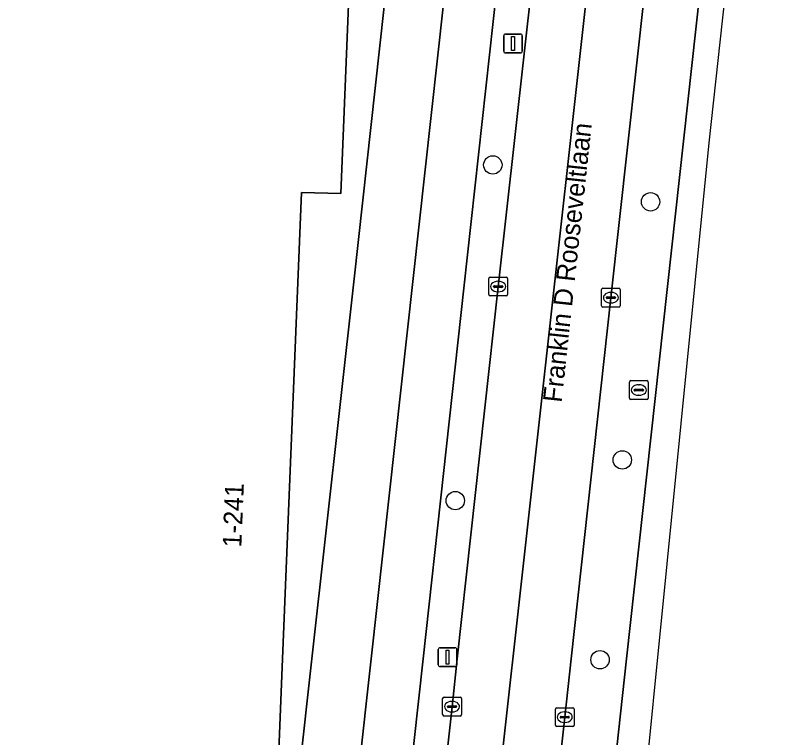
# Model space of a CAD drawing. Extents: x 160888 to 161385, y 386490 to 386908.
# Drawn here: x 161343.3 to 161384.03, y 386745.8 to 386784.23 of the extents above; entities that cross this region are included whole.
import ezdxf

# ---------------------------------------------------------------- set-up
doc = ezdxf.new("R2010")
doc.units = 0
for name, color, linetype in [('IMGEO_Berm_groen', 7, 'Continuous'), ('IMGEO_Boom', 7, 'Continuous'), ('IMGEO_Erf', 7, 'Continuous'), ('IMGEO_Fietspad_gesloten', 7, 'Continuous'), ('IMGEO_Kolk', 7, 'Continuous'), ('IMGEO_Lichtmast', 7, 'Continuous'), ('IMGEO_Openbare_ruimte_label', 7, 'Continuous'), ('IMGEO_Pand', 7, 'Continuous'), ('IMGEO_Pand_nummerreeks', 7, 'Continuous'), ('IMGEO_Rijbaan_lokaal_gesloten', 7, 'Continuous'), ('IMGEO_Rioolput', 7, 'Continuous'), ('IMGEO_Voetpad_open', 7, 'Continuous')]:
    doc.layers.add(name, color=color, linetype=linetype)

msp = doc.modelspace()

# ---------------------------------------------------------------- linework, layer by layer
at = {"layer": 'IMGEO_Berm_groen'}
for points in [[(161373.644, 386813.676), (161372.043, 386813.873), (161371.658, 386810.524), (161367.179, 386769.719), (161365.004, 386750), (161363.779, 386738.891), (161362.922, 386732.791), (161361.755, 386725.593)], [(161368.999, 386769.786), (161371.264, 386790.142), (161373.505, 386810.507), (161373.654, 386811.717), (161373.847, 386812.791), (161373.931, 386813.306)], [(161379.812, 386812.698), (161379.518, 386809.955), (161377.255, 386789.585), (161374.998, 386769.209), (161372.886, 386750), (161372.544, 386746.889), (161370.136, 386725.225)], [(161373.249, 386724.98), (161374.104, 386730.63), (161374.587, 386736.651), (161374.749, 386740.065), (161375.512, 386747.068), (161375.835, 386750), (161380.179, 386789.468)], [(161364.089, 386725.334), (161364.11, 386725.435), (161364.289, 386727.081), (161366.545, 386747.443), (161366.826, 386750), (161368.999, 386769.786)]]:
    msp.add_lwpolyline(points, dxfattribs=at)
at = {"layer": 'IMGEO_Boom'}
for centre in [(161368.715, 386776.272), (161377.108, 386774.309), (161375.606, 386760.578), (161366.718, 386758.41), (161374.42, 386749.942)]:
    msp.add_circle(centre, 0.489, dxfattribs=at)
at = {"layer": 'IMGEO_Erf'}
msp.add_lwpolyline([(161362.7, 386825.861), (161360.635, 386774.751), (161358.531, 386774.8), (161357.522, 386750), (161357.179, 386741.563), (161353.533, 386741.712), (161353.387, 386738.115), (161355.121, 386738.044), (161354.593, 386725.304), (161356.352, 386725.232), (161358.409, 386743.907), (161359.085, 386750), (161361.328, 386770.209), (161365.845, 386811.132), (161367.463, 386825.61)], close=True, dxfattribs=at)
at = {"layer": 'IMGEO_Fietspad_gesloten'}
for points in [[(161367.179, 386769.719), (161371.658, 386810.524), (161372.043, 386813.873), (161372.393, 386816.844), (161372.67, 386819.166), (161373.331, 386824.71), (161370.327, 386824.774)], [(161370.409, 386823.612), (161369.942, 386819.493), (161368.96, 386810.871), (161362.241, 386750), (161360.898, 386737.834), (161359.269, 386727.112)], [(161361.755, 386725.593), (161362.922, 386732.791), (161363.779, 386738.891), (161365.004, 386750), (161367.179, 386769.719)]]:
    msp.add_lwpolyline(points, dxfattribs=at)
at = {"layer": 'IMGEO_Kolk'}
for p, q in [((161368.574, 386770.299), (161369.426, 386770.299)), ((161368.499, 386769.373), (161368.499, 386770.225)), ((161368.987, 386770.079), (161369.012, 386770.079)), ((161369.5, 386770.225), (161369.5, 386769.373)), ((161368.758, 386769.793), (161368.758, 386769.805)), ((161369.196, 386769.756), (161368.798, 386769.756)), ((161368.801, 386769.842), (161369.199, 386769.842)), ((161369.01, 386769.519), (161368.985, 386769.519)), ((161369.242, 386769.805), (161369.242, 386769.793)), ((161374.497, 386768.783), (161374.497, 386769.635)), ((161374.572, 386769.709), (161375.424, 386769.709)), ((161374.985, 386769.489), (161375.01, 386769.489)), ((161375.498, 386769.635), (161375.498, 386768.783)), ((161369.426, 386769.299), (161368.574, 386769.299)), ((161374.756, 386769.203), (161374.756, 386769.215)), ((161375.194, 386769.166), (161374.796, 386769.166)), ((161374.799, 386769.252), (161375.197, 386769.252)), ((161375.24, 386769.215), (161375.24, 386769.203)), ((161375.424, 386768.709), (161374.572, 386768.709)), ((161375.008, 386768.929), (161374.983, 386768.929)), ((161366.044, 386747.022), (161366.044, 386747.874)), ((161366.119, 386747.948), (161366.971, 386747.948)), ((161367.045, 386747.874), (161367.045, 386747.022)), ((161366.303, 386747.442), (161366.303, 386747.454)), ((161366.346, 386747.491), (161366.744, 386747.491)), ((161366.532, 386747.728), (161366.557, 386747.728)), ((161366.787, 386747.454), (161366.787, 386747.442)), ((161366.741, 386747.405), (161366.343, 386747.405)), ((161366.555, 386747.168), (161366.53, 386747.168)), ((161372.043, 386746.463), (161372.043, 386747.315)), ((161372.118, 386747.389), (161372.97, 386747.389)), ((161372.531, 386747.169), (161372.556, 386747.169)), ((161373.044, 386747.315), (161373.044, 386746.463)), ((161366.971, 386746.948), (161366.119, 386746.948)), ((161372.302, 386746.883), (161372.302, 386746.895)), ((161372.74, 386746.846), (161372.342, 386746.846)), ((161372.345, 386746.932), (161372.743, 386746.932)), ((161372.786, 386746.895), (161372.786, 386746.883)), ((161372.97, 386746.389), (161372.118, 386746.389)), ((161372.554, 386746.609), (161372.529, 386746.609))]:
    msp.add_line(p, q, dxfattribs=at)
for points in [[(161368.574, 386770.299), (161369.426, 386770.299)], [(161368.499, 386769.373), (161368.499, 386770.225)], [(161369.5, 386770.225), (161369.5, 386769.373)], [(161374.497, 386768.783), (161374.497, 386769.635)], [(161374.572, 386769.709), (161375.424, 386769.709)], [(161375.498, 386769.635), (161375.498, 386768.783)], [(161369.426, 386769.299), (161368.574, 386769.299)], [(161375.424, 386768.709), (161374.572, 386768.709)], [(161366.044, 386747.022), (161366.044, 386747.874)], [(161366.119, 386747.948), (161366.971, 386747.948)], [(161367.045, 386747.874), (161367.045, 386747.022)], [(161372.043, 386746.463), (161372.043, 386747.315)], [(161372.118, 386747.389), (161372.97, 386747.389)], [(161373.044, 386747.315), (161373.044, 386746.463)], [(161366.971, 386746.948), (161366.119, 386746.948)], [(161372.97, 386746.389), (161372.118, 386746.389)]]:
    msp.add_lwpolyline(points, dxfattribs=at)
for centre, radius, start, end in [((161368.576, 386770.223), 0.0765, 91.552, 178.448), ((161368.576, 386770.223), 0.0765, 91.552, 178.448), ((161369.424, 386770.223), 0.0765, 1.552, 88.448), ((161369.424, 386770.223), 0.0765, 1.552, 88.448), ((161368.798, 386769.802), 0.0403, 85.8775, 175.7526), ((161368.795, 386769.792), 0.0366, 178.938, 274.7102), ((161369.199, 386769.799), 0.043, 264.8664, 352.4533), ((161369.203, 386769.804), 0.0386, 1.7309, 96.639), ((161374.574, 386769.633), 0.0765, 91.552, 178.448), ((161374.574, 386769.633), 0.0765, 91.552, 178.448), ((161375.422, 386769.633), 0.0765, 1.552, 88.448), ((161375.422, 386769.633), 0.0765, 1.552, 88.448), ((161368.576, 386769.375), 0.0765, 181.552, 268.448), ((161368.576, 386769.375), 0.0765, 181.552, 268.448), ((161369.424, 386769.375), 0.0765, 271.552, 358.448), ((161369.424, 386769.375), 0.0765, 271.552, 358.448), ((161374.796, 386769.212), 0.0403, 85.8775, 175.7526), ((161374.793, 386769.202), 0.0366, 178.938, 274.7102), ((161375.197, 386769.209), 0.043, 264.8664, 352.4533), ((161375.201, 386769.214), 0.0386, 1.7309, 96.639), ((161374.574, 386768.785), 0.0765, 181.552, 268.448), ((161374.574, 386768.785), 0.0765, 181.552, 268.448), ((161375.422, 386768.785), 0.0765, 271.552, 358.448), ((161375.422, 386768.785), 0.0765, 271.552, 358.448), ((161366.121, 386747.872), 0.0765, 91.552, 178.448), ((161366.121, 386747.872), 0.0765, 91.552, 178.448), ((161366.969, 386747.872), 0.0765, 1.552, 88.448), ((161366.969, 386747.872), 0.0765, 1.552, 88.448), ((161366.343, 386747.451), 0.0403, 85.8775, 175.7526), ((161366.748, 386747.453), 0.0386, 1.7309, 96.639), ((161366.34, 386747.441), 0.0366, 178.938, 274.7102), ((161366.744, 386747.448), 0.043, 264.8664, 352.4533), ((161372.12, 386747.313), 0.0765, 91.552, 178.448), ((161372.12, 386747.313), 0.0765, 91.552, 178.448), ((161372.968, 386747.313), 0.0765, 1.552, 88.448), ((161372.968, 386747.313), 0.0765, 1.552, 88.448), ((161366.121, 386747.024), 0.0765, 181.552, 268.448), ((161366.121, 386747.024), 0.0765, 181.552, 268.448), ((161366.969, 386747.024), 0.0765, 271.552, 358.448), ((161366.969, 386747.024), 0.0765, 271.552, 358.448), ((161372.342, 386746.892), 0.0403, 85.8775, 175.7526), ((161372.339, 386746.882), 0.0366, 178.938, 274.7102), ((161372.743, 386746.889), 0.043, 264.8664, 352.4533), ((161372.747, 386746.894), 0.0386, 1.7309, 96.639), ((161372.12, 386746.465), 0.0765, 181.552, 268.448), ((161372.12, 386746.465), 0.0765, 181.552, 268.448), ((161372.968, 386746.465), 0.0765, 271.552, 358.448), ((161372.968, 386746.465), 0.0765, 271.552, 358.448)]:
    msp.add_arc(centre, radius, start, end, dxfattribs=at)
for centre, major_axis, ratio, start_param, end_param in [((161368.986, 386769.799), (-0.387, 0.002), 0.722429, 4.712389, 7.853982), ((161369.011, 386769.799), (-0.39, 0.002), 0.717154, 1.570796, 4.712389), ((161374.984, 386769.209), (-0.387, 0.002), 0.722429, 4.712389, 7.853982), ((161375.009, 386769.209), (-0.39, 0.002), 0.717154, 1.570796, 4.712389), ((161366.531, 386747.448), (-0.387, 0.002), 0.722429, 4.712389, 7.853982), ((161366.556, 386747.448), (-0.39, 0.002), 0.717154, 1.570796, 4.712389), ((161372.53, 386746.889), (-0.387, 0.002), 0.722429, 4.712389, 7.853982), ((161372.555, 386746.889), (-0.39, 0.002), 0.717154, 1.570796, 4.712389)]:
    msp.add_ellipse(centre, major_axis=major_axis, ratio=ratio, start_param=start_param, end_param=end_param, dxfattribs=at)
at = {"layer": 'IMGEO_Lichtmast'}
for p, q in [((161369.295, 386782.332), (161369.295, 386783.132)), ((161369.295, 386783.132), (161369.295, 386782.332)), ((161369.395, 386783.232), (161370.185, 386783.232)), ((161370.185, 386783.232), (161369.395, 386783.232)), ((161370.285, 386783.132), (161370.285, 386782.332)), ((161370.285, 386782.332), (161370.285, 386783.132)), ((161370.185, 386782.232), (161369.395, 386782.232)), ((161369.395, 386782.232), (161370.185, 386782.232)), ((161365.81, 386749.681), (161365.81, 386750.481)), ((161365.81, 386750.481), (161365.81, 386749.681)), ((161365.91, 386750.581), (161366.7, 386750.581)), ((161366.7, 386750.581), (161365.91, 386750.581)), ((161366.8, 386750.481), (161366.8, 386749.681)), ((161366.8, 386749.681), (161366.8, 386750.481)), ((161366.7, 386749.581), (161365.91, 386749.581)), ((161365.91, 386749.581), (161366.7, 386749.581))]:
    msp.add_line(p, q, dxfattribs=at)
for points in [[(161369.715, 386783.107), (161369.865, 386783.107), (161369.865, 386782.357), (161369.715, 386782.357), (161369.715, 386783.107)], [(161366.23, 386750.456), (161366.38, 386750.456), (161366.38, 386749.706), (161366.23, 386749.706), (161366.23, 386750.456)]]:
    msp.add_lwpolyline(points, dxfattribs=at)
for centre, start, end in [((161369.395, 386783.132), 90, 180), ((161369.395, 386783.132), 90, 180), ((161370.185, 386783.132), 0, 90), ((161370.185, 386783.132), 360, 90), ((161369.395, 386782.332), 180, 270), ((161369.395, 386782.332), 180, 270), ((161370.185, 386782.332), 270, 0), ((161370.185, 386782.332), 270, 0), ((161365.91, 386750.481), 90, 180), ((161365.91, 386750.481), 90, 180), ((161366.7, 386750.481), 0, 90), ((161366.7, 386750.481), 360, 90), ((161365.91, 386749.681), 180, 270), ((161365.91, 386749.681), 180, 270), ((161366.7, 386749.681), 270, 0), ((161366.7, 386749.681), 270, 0)]:
    msp.add_arc(centre, 0.1, start, end, dxfattribs=at)
at = {"layer": 'IMGEO_Pand'}
msp.add_lwpolyline([(161348.445, 386826.44), (161348.244, 386822.153), (161340.54, 386822.467), (161340.189, 386813.832), (161342.162, 386813.752), (161340.481, 386772.426), (161338.482, 386772.507), (161337.567, 386750), (161337.283, 386743.017), (161335.309, 386743.098), (161334.593, 386726.104), (161334.801, 386726.096), (161354.391, 386725.312), (161354.593, 386725.304), (161355.121, 386738.044), (161353.387, 386738.115), (161353.533, 386741.712), (161357.179, 386741.563), (161357.522, 386750), (161358.531, 386774.8), (161360.635, 386774.751), (161362.7, 386825.861)], close=True, dxfattribs=at)
at = {"layer": 'IMGEO_Rijbaan_lokaal_gesloten'}
msp.add_lwpolyline([(161368.323, 386736.898), (161376.784, 386813.011), (161373.931, 386813.306), (161373.847, 386812.791), (161373.654, 386811.717), (161373.505, 386810.507), (161371.264, 386790.142), (161368.999, 386769.786), (161366.826, 386750), (161366.545, 386747.443), (161364.289, 386727.081), (161364.11, 386725.435), (161364.089, 386725.334), (161363.501, 386722.441), (161363.674, 386722.44)], dxfattribs=at)
for points in [[(161372.544, 386746.889), (161372.886, 386750), (161374.998, 386769.209), (161377.255, 386789.585), (161379.518, 386809.955), (161379.812, 386812.698), (161376.784, 386813.011), (161368.323, 386736.898), (161366.259, 386718.291), (161369.328, 386718.155), (161369.778, 386722.177), (161370.136, 386725.225)], [(161374.289, 386717.883), (161380.225, 386777.448), (161384.035, 386812.351), (161382.706, 386812.365), (161380.179, 386789.468), (161375.835, 386750), (161375.512, 386747.068), (161374.749, 386740.065), (161374.587, 386736.651), (161374.104, 386730.63), (161373.249, 386724.98), (161372.62, 386721.998), (161371.548, 386717.899)]]:
    msp.add_lwpolyline(points, close=True, dxfattribs=at)
at = {"layer": 'IMGEO_Rioolput'}
for p, q in [((161375.983, 386763.867), (161375.983, 386764.719)), ((161376.058, 386764.793), (161376.91, 386764.793)), ((161376.471, 386764.573), (161376.496, 386764.573)), ((161376.984, 386764.719), (161376.984, 386763.867)), ((161376.242, 386764.287), (161376.242, 386764.299)), ((161376.68, 386764.25), (161376.282, 386764.25)), ((161376.285, 386764.336), (161376.683, 386764.336)), ((161376.726, 386764.299), (161376.726, 386764.287)), ((161376.91, 386763.793), (161376.058, 386763.793)), ((161376.494, 386764.013), (161376.469, 386764.013))]:
    msp.add_line(p, q, dxfattribs=at)
for points in [[(161375.983, 386763.867), (161375.983, 386764.719)], [(161376.058, 386764.793), (161376.91, 386764.793)], [(161376.984, 386764.719), (161376.984, 386763.867)], [(161376.91, 386763.793), (161376.058, 386763.793)]]:
    msp.add_lwpolyline(points, dxfattribs=at)
for centre, radius, start, end in [((161376.06, 386764.717), 0.0765, 91.552, 178.448), ((161376.06, 386764.717), 0.0765, 91.552, 178.448), ((161376.908, 386764.717), 0.0765, 1.552, 88.448), ((161376.908, 386764.717), 0.0765, 1.552, 88.448), ((161376.282, 386764.296), 0.0403, 85.8775, 175.7526), ((161376.279, 386764.286), 0.0366, 178.938, 274.7102), ((161376.683, 386764.293), 0.043, 264.8664, 352.4533), ((161376.687, 386764.298), 0.0386, 1.7309, 96.639), ((161376.06, 386763.869), 0.0765, 181.552, 268.448), ((161376.06, 386763.869), 0.0765, 181.552, 268.448), ((161376.908, 386763.869), 0.0765, 271.552, 358.448), ((161376.908, 386763.869), 0.0765, 271.552, 358.448)]:
    msp.add_arc(centre, radius, start, end, dxfattribs=at)
for centre, major_axis, ratio, start_param, end_param in [((161376.47, 386764.293), (-0.387, 0.002), 0.722429, 4.712389, 7.853982), ((161376.495, 386764.293), (-0.39, 0.002), 0.717154, 1.570796, 4.712389)]:
    msp.add_ellipse(centre, major_axis=major_axis, ratio=ratio, start_param=start_param, end_param=end_param, dxfattribs=at)
at = {"layer": 'IMGEO_Voetpad_open'}
for points in [[(161370.327, 386824.774), (161367.463, 386825.61), (161365.845, 386811.132), (161361.328, 386770.209), (161359.085, 386750), (161358.409, 386743.907), (161356.352, 386725.232), (161356.013, 386721.722)], [(161360.898, 386737.834), (161362.241, 386750), (161368.96, 386810.871), (161369.942, 386819.493), (161370.409, 386823.612)]]:
    msp.add_lwpolyline(points, dxfattribs=at)

# ---------------------------------------------------------------- texts
at = {"layer": 'IMGEO_Openbare_ruimte_label'}
msp.add_text('Franklin D Rooseveltlaan', height=1, rotation=83.799, dxfattribs=at).set_placement((161372.372, 386763.601))
at = {"layer": 'IMGEO_Pand_nummerreeks'}
msp.add_text('1-241', height=1, rotation=87.6706, dxfattribs=at).set_placement((161355.33, 386755.908))

doc.saveas('drawing.dxf')
